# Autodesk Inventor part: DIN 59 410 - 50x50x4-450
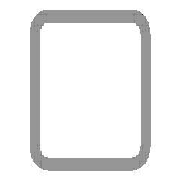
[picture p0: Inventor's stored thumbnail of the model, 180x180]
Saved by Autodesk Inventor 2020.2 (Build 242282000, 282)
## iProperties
Manager: www.cadconsulting.pl
Company: Fabian Stasiak CAD Consulting
Created: 2015-01
Part Number: DIN 59 410 - 50x50x4-450
Material: Stal, miękka
Description: Rurki stalowe o przekroju kwadratowym formowane na gorąco
Document SubType Name: Modellieren
Standard: DIN
Designer: F.Stasiak
Standards Organization: DIN
Language: pl-PL
Size Designation: 50x50x4
Categories: <MemberInstance><Categories><Category DisplayName="Kształtowniki konstrukcyjne" InternalName="089c4875-fa83-4c05-b084-43b9cc11f5ed" Mnemonic="GRDR"><CategoryPar
Stock Number: 50x50x4
Density: 7.85 g/cm^3
Appearance: Częściowo polerowana
Mass: 2508.91 g
Surface Area: 1611.93 cm^2
Volume: 319.606 cm^3
Catalog Web Link: www.expertbooks.pl
_CCFamilyMember: 40
_CCFamilyDisplayName: DIN 59410 (Kwadrat) - Rurki stalowe o przekroju kwadratowym formowane na gorąco
_FrameMemberDoc: Frame Member File
_Version: 15.0.0
_GetPNFromCC: 1
G_W: 50,000 mm
G_H: 50,000 mm
G_L: 450,000 mm
+A7E5AA02-5026-4A57-9C61-9FFF266A17F5+CUTDETAIL3: Wytnij
+1CFAA338-C828-4B30-87E5-B78495DB4060+CUTDETAIL4: Wytnij
IsCustomPart: 1
Author: F.Stasiak
Subject: Zbiór ćwiczeń. Autodesk Inventor 2020. Kurs Professional
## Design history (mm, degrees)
node "Płaszczyzna początkowa"
node "Płaszczyzna końcowa"
sketch "Szkic"
  geometry: L1 (-17, 25)-(17, 25); L2 (25, 17)-(25, -17); L3 (17, -25)-(-17, -25); L4 (-25, -17)-(-25, 17); L5 (-37.32, 0)-(37.32, 0) reference; L6 (0, -37.32)-(0, 37.32) reference; L7 (-17, 21)-(17, 21); L8 (21, 17)-(21, -17); L9 (17, -21)-(-17, -21); L10 (-21, -17)-(-21, 17); A1 r 8 centre (-17, 17) between (-17, 25) and (-25, 17); A2 r 8 centre (17, 17) between (25, 17) and (17, 25); A3 r 8 centre (17, -17) between (17, -25) and (25, -17); A4 r 8 centre (-17, -17) between (-25, -17) and (-17, -25); A5 r 4 centre (-17, 17) between (-17, 21) and (-21, 17); A6 r 4 centre (17, 17) between (21, 17) and (17, 21); A7 r 4 centre (17, -17) between (17, -21) and (21, -17); A8 r 4 centre (-17, -17) between (-21, -17) and (-17, -21); 3 further points
  constraints: 16 end point, 16 point on circle, 8 centre point, 8 tangent, 6 point on line, 4 parallel, 3 equal radius, 3 perpendicular, 1 horizontal, 7 other
  dimensions: "b" = 50 distance of point (-25, 25) point (25, 25); "msp_r" = 8 radius of A1 (= 2 x ParT); "d8" = 25 distance between parallel lines of L4 L6 (= d9); "d9" = 25 distance between parallel lines of L3 L5 (= 0.5 x b); "d10" = 4 distance between parallel lines of L3 L9 (= ParT)
extrude "Bryła" new body sketch "Szkic" taper "d4" = 0 deg; stored distance "NLG" = 10
node "Driven Length"
  sketch "Sketch2"
    geometry: L1 (0, 0)-(10, 0) reference
    constraints: 2 end point, 1 horizontal
  workplane "Work Plane3"
  sketch "Sketch3"
    geometry: L1 (-2, 25)-(12, 25) reference; L2 (-2, 475)-(12, 475) reference
    dimensions: "d14" = 450 distance between parallel lines of L1 L2 (derived)
node "Płaszczyzna konstrukcyjna6"
feature "Podział3"
node "Płaszczyzna konstrukcyjna7"
feature "Podział4"
body "Solid1"
other parameters: "ParT" = 4, "G_OFFSET_START" = -25 [user parameter; used in 1 equation term], "G_OFFSET_END" = 25 [user parameter; used in 1 equation term], "d11" = 25 (= -G_OFFSET_START), "d12" = 475 (= G_OFFSET_END + B_L), "G_L" = 450 (= d14) [user parameter], "d13" = 90 deg
